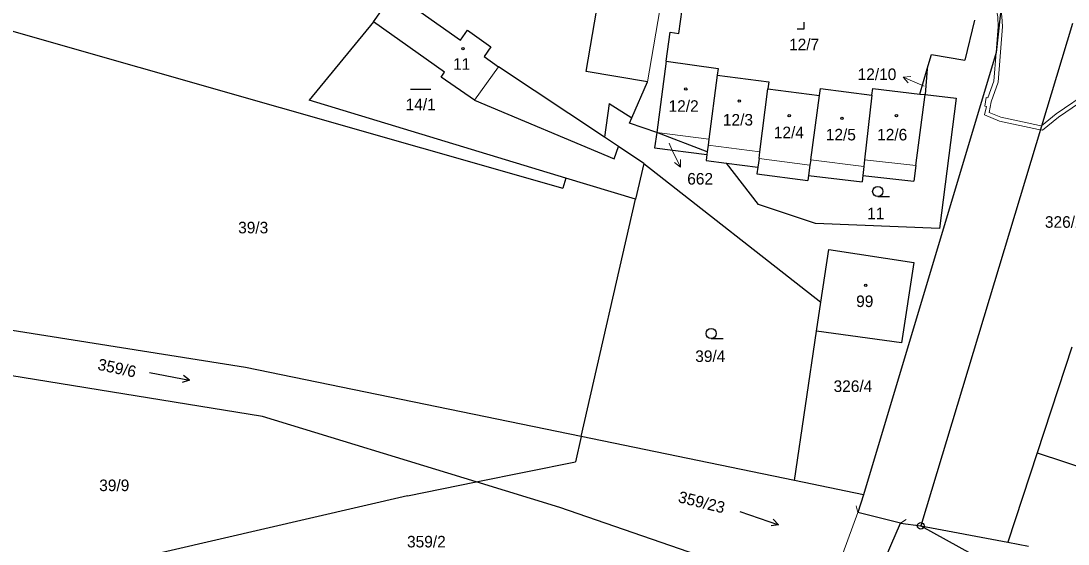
# Model space of a CAD drawing. Extents: x -759947 to -757003, y -1019641 to -1017100.
# Drawn here: x -758095.4 to -757941.4, y -1019052.2 to -1018975.4 of the extents above; entities that cross this region are included whole.
import ezdxf
from ezdxf.enums import TextEntityAlignment as Align

# ---------------------------------------------------------------- set-up
doc = ezdxf.new("R2010")
doc.units = 0
doc.header["$LTSCALE"] = 0.68
for name, color, linetype, lineweight in [('1', 7, 'Continuous', 25), ('13', 7, 'Continuous', 13), ('3', 7, 'Continuous', 25), ('4', 7, 'Continuous', 13), ('5', 7, 'Continuous', 25), ('7', 7, 'Continuous', 13), ('8', 7, 'Continuous', 25)]:
    doc.layers.add(name, color=color, linetype=linetype, lineweight=lineweight)
doc.layers.add('2', color=7, linetype='Continuous')

msp = doc.modelspace()

# ---------------------------------------------------------------- linework, layer by layer
at = {"layer": '1'}
for p, q in [((-757949.4, -1018956.77), (-757951.94, -1018980.02)), ((-758012.27, -1018982.78), (-758008.32, -1018959.61)), ((-757998.62, -1018977.2), (-757997.84, -1018971.35)), ((-758106.97, -1018973.92), (-758015.69, -1018999.93)), ((-758043.52, -1018975.49), (-758052.98, -1018986.98)), ((-758033.09, -1018982.87), (-758043.52, -1018975.49)), ((-757940.73, -1018975.74), (-757963.05, -1019049.56)), ((-757955.12, -1018975.23), (-757956.58, -1018981.14)), ((-758030.72, -1018978.17), (-758029.69, -1018976.72)), ((-758029.69, -1018976.72), (-758026.25, -1018979.16)), ((-758026.25, -1018979.16), (-758027.27, -1018980.6)), ((-758027.27, -1018980.6), (-758025.13, -1018982.11)), ((-757951.94, -1018980.02), (-757971.49, -1019044.98)), ((-757962.12, -1018982.42), (-757961.49, -1018980.28)), ((-757961.49, -1018980.28), (-757956.58, -1018981.14)), ((-758009.57, -1018992.46), (-758025.13, -1018982.11)), ((-758000.48, -1018981.28), (-758001.88, -1018991.74)), ((-758000.48, -1018981.28), (-757992.85, -1018982.36)), ((-757992.85, -1018982.36), (-757992.98, -1018983.35)), ((-757963.2, -1018986.1), (-757962.12, -1018982.42)), ((-757962.12, -1018982.42), (-757962.41, -1018986.19)), ((-758033.6, -1018983.61), (-758033.09, -1018982.87)), ((-758028.67, -1018987.01), (-758033.6, -1018983.61)), ((-758003.24, -1018984.32), (-758012.27, -1018982.78)), ((-757992.98, -1018983.35), (-757994.19, -1018992.73)), ((-757992.98, -1018983.35), (-757985.39, -1018984.33)), ((-758005.54, -1018989.59), (-758003.24, -1018984.32)), ((-757986.7, -1018994.58), (-757985.52, -1018985.32)), ((-757985.39, -1018984.33), (-757985.52, -1018985.32)), ((-757985.52, -1018985.32), (-757977.93, -1018986.3)), ((-757977.93, -1018986.3), (-757977.81, -1018985.3)), ((-757977.81, -1018985.3), (-757970.22, -1018986.28)), ((-757970.22, -1018986.28), (-757970.09, -1018985.29)), ((-757970.09, -1018985.29), (-757963.2, -1018986.1)), ((-758015.22, -1018998.44), (-758052.98, -1018986.98)), ((-758028.67, -1018987.01), (-758008.12, -1018995.64)), ((-757979.23, -1018995.77), (-757977.93, -1018986.3)), ((-757970.22, -1018986.28), (-757971.3, -1018995.77)), ((-757963.76, -1018996.62), (-757962.41, -1018986.19)), ((-757963.2, -1018986.1), (-757962.41, -1018986.19)), ((-757962.41, -1018986.19), (-757957.84, -1018986.73)), ((-758008.85, -1018987.51), (-758009.57, -1018992.46)), ((-758008.85, -1018987.51), (-758005.54, -1018989.59)), ((-758005.89, -1018990.39), (-758005.54, -1018989.59)), ((-758001.88, -1018991.74), (-758005.89, -1018990.39)), ((-758001.88, -1018991.74), (-758002.19, -1018994.02)), ((-757994.44, -1018994.61), (-758001.88, -1018991.74)), ((-758007.5, -1018993.83), (-758009.57, -1018992.46)), ((-757994.19, -1018992.73), (-757994.31, -1018993.59)), ((-758008.12, -1018995.64), (-758007.5, -1018993.83)), ((-758003.78, -1018996.31), (-758007.5, -1018993.83)), ((-758002.19, -1018994.02), (-757994.49, -1018995.01)), ((-757994.44, -1018994.61), (-757994.49, -1018995.01)), ((-757994.31, -1018993.59), (-757994.44, -1018994.61)), ((-757986.83, -1018995.56), (-757986.7, -1018994.58)), ((-758003.78, -1018996.31), (-758004.98, -1019001.55)), ((-758003.78, -1018996.31), (-757977.73, -1019016.71)), ((-757994.49, -1018995.01), (-757994.6, -1018995.87)), ((-757994.6, -1018995.87), (-757991.63, -1018996.26)), ((-757991.63, -1018996.26), (-757987, -1018996.86)), ((-757986.91, -1019002.32), (-757991.63, -1018996.26)), ((-757986.83, -1018995.56), (-757987, -1018996.86)), ((-757979.23, -1018995.77), (-757979.34, -1018996.53)), ((-757971.3, -1018995.77), (-757971.41, -1018996.73)), ((-757987, -1018996.86), (-757987.13, -1018997.84)), ((-757987.13, -1018997.84), (-757979.64, -1018998.81)), ((-757979.34, -1018996.53), (-757979.54, -1018998.05)), ((-757971.41, -1018996.73), (-757971.56, -1018998.06)), ((-757963.76, -1018996.62), (-757964.06, -1018998.9)), ((-758015.22, -1018998.44), (-758015.69, -1018999.93)), ((-758004.98, -1019001.55), (-758015.22, -1018998.44)), ((-757979.54, -1018998.05), (-757979.64, -1018998.81)), ((-757979.54, -1018998.05), (-757971.67, -1018999.02)), ((-757971.56, -1018998.06), (-757971.67, -1018999.02)), ((-757971.56, -1018998.06), (-757964.06, -1018998.9)), ((-758012.99, -1019036.45), (-758004.98, -1019001.55)), ((-757978.53, -1019005.15), (-757986.91, -1019002.32)), ((-757977.73, -1019016.71), (-757976.58, -1019008.96)), ((-757976.58, -1019008.96), (-757964.07, -1019010.84)), ((-757964.07, -1019010.84), (-757965.88, -1019022.65)), ((-758062.35, -1019026.31), (-758120.22, -1019017.1)), ((-757978.36, -1019020.93), (-757977.73, -1019016.71)), ((-757981.62, -1019042.9), (-757978.36, -1019020.93)), ((-757965.88, -1019022.65), (-757978.36, -1019020.93)), ((-757940.84, -1019023.32), (-757945.93, -1019038.84)), ((-758059.87, -1019033.48), (-758107.42, -1019025.81)), ((-758012.99, -1019036.45), (-758062.35, -1019026.31)), ((-758028.41, -1019043.1), (-758059.87, -1019033.48)), ((-758012.99, -1019036.45), (-758013.84, -1019040.15)), ((-757981.62, -1019042.9), (-758012.99, -1019036.45)), ((-757945.93, -1019038.84), (-757950.23, -1019051.96)), ((-757945.93, -1019038.84), (-757935.66, -1019042.2)), ((-758028.41, -1019043.1), (-758013.84, -1019040.15)), ((-758038.51, -1019045.14), (-758028.41, -1019043.1)), ((-758016.14, -1019046.85), (-758028.41, -1019043.1)), ((-757971.49, -1019044.98), (-757981.62, -1019042.9)), ((-758038.51, -1019045.14), (-758080.47, -1019054.84)), ((-757971.49, -1019044.98), (-757972.28, -1019047.6)), ((-757976.98, -1019060.34), (-758016.14, -1019046.85)), ((-757966.03, -1019049.17), (-757972.28, -1019047.6)), ((-757971.99, -1019062.81), (-757966.03, -1019049.17)), ((-757966.03, -1019049.17), (-757963.05, -1019049.56)), ((-757963.05, -1019049.56), (-757950.23, -1019051.96)), ((-757963.05, -1019049.56), (-757891.09, -1019089.05)), ((-757950.23, -1019051.96), (-757947.21, -1019052.53))]:
    msp.add_line(p, q, dxfattribs=at)
for points in [[(-758043.52, -1018975.49), (-758040.52, -1018971.25), (-758030.72, -1018978.17)], [(-758000.48, -1018981.28), (-757999.91, -1018977.03), (-757998.62, -1018977.2)], [(-757957.84, -1018986.73), (-757960.29, -1019005.87), (-757978.53, -1019005.15)]]:
    msp.add_lwpolyline(points, dxfattribs=at)
at = {"layer": '13'}
for points in [[(-757949.75, -1018951.37), (-757949.89, -1018951.35), (-757949.9, -1018951.2), (-757950.15, -1018951.21), (-757950.1, -1018952.08), (-757949.85, -1018952.07), (-757949.86, -1018951.96), (-757949.76, -1018951.97), (-757949.97, -1018955.93), (-757950.52, -1018963.51), (-757951.84, -1018974.04), (-757951.73, -1018974.77), (-757951.64, -1018976.16), (-757951.94, -1018980.02), (-757949.4, -1018956.77), (-757949.71, -1018945.51)], [(-757949.92, -1018963.57), (-757949.4, -1018956.77), (-757951.94, -1018980.02), (-757952.28, -1018984.22), (-757953.17, -1018986.65), (-757953.42, -1018986.61), (-757953.62, -1018987.89), (-757953.38, -1018987.93), (-757953.69, -1018989.17), (-757951.47, -1018990.08), (-757945.75, -1018991.29), (-757945.45, -1018991.35), (-757945.27, -1018990.76), (-757945.3, -1018990.78), (-757945.59, -1018990.71), (-757951.29, -1018989.5), (-757953.01, -1018988.81), (-757952.7, -1018987.26), (-757951.68, -1018984.34), (-757951.04, -1018976.16), (-757951.13, -1018974.71), (-757951.24, -1018974.04)], [(-757930.45, -1018979.41), (-757934.39, -1018982.12), (-757938.07, -1018985.58), (-757943.15, -1018989.03), (-757945.27, -1018990.76), (-757945.45, -1018991.35), (-757945.14, -1018991.42), (-757942.79, -1018989.51), (-757937.69, -1018986.04), (-757934.01, -1018982.58), (-757930.29, -1018980.03), (-757928.65, -1018980.19), (-757928.46, -1018979.61)]]:
    msp.add_lwpolyline(points, close=True, dxfattribs=at)
at = {"layer": '3'}
for p, q in [((-758038.088, -1018985.36), (-758035.088, -1018985.36)), ((-757969.373, -1019001.18), (-757967.623, -1019001.18)), ((-757993.863, -1019022.04), (-757992.113, -1019022.04)), ((-758070.6, -1019028.164), (-758071.655, -1019028.47)), ((-757983.97, -1019049.39), (-757985.057, -1019049.546))]:
    msp.add_line(p, q, dxfattribs=at)
for points in [[(-757981.201, -1018976.54), (-757980.2, -1018976.54), (-757980.2, -1018975.54)], [(-758076.49, -1019027.019), (-758070.6, -1019028.164), (-758071.463, -1019027.485)], [(-757989.643, -1019047.437), (-757983.97, -1019049.39), (-757984.731, -1019048.598)]]:
    msp.add_lwpolyline(points, dxfattribs=at)
for centre in [(-757969.3729, -1019000.4298), (-757993.8629, -1019021.2898)]:
    msp.add_circle(centre, 0.75, dxfattribs=at)
at = {"layer": '4'}
for p, q in [((-757998.8, -1018958.51), (-758003.24, -1018984.32)), ((-758028.67, -1018987.01), (-758025.13, -1018982.11)), ((-757994.19, -1018992.73), (-758001.88, -1018991.74)), ((-757994.31, -1018993.59), (-757986.7, -1018994.58)), ((-757986.83, -1018995.56), (-757979.34, -1018996.53)), ((-757971.41, -1018996.73), (-757979.23, -1018995.77)), ((-757963.76, -1018996.62), (-757971.3, -1018995.77)), ((-757972.538, -1019046.634), (-757972.28, -1019047.599)), ((-757976.98, -1019060.34), (-757972.28, -1019047.6)), ((-757965.191, -1019048.626), (-757966.029, -1019049.17))]:
    msp.add_line(p, q, dxfattribs=at)
at = {"layer": '5'}
for centre in [(-758030.3768, -1018979.4492), (-757997.5968, -1018985.3492), (-757989.7368, -1018987.1392), (-757982.3968, -1018989.2592), (-757974.6368, -1018989.6892), (-757966.6168, -1018989.2992), (-757971.1368, -1019014.2092)]:
    msp.add_circle(centre, 0.175, dxfattribs=at)
at = {"layer": '7'}
for p, q in [((-757965.632, -1018983.607), (-757964.906, -1018984.46)), ((-757998.374, -1018996.837), (-757998.363, -1018995.718))]:
    msp.add_line(p, q, dxfattribs=at)
for points in [[(-757962.53, -1018984.92), (-757962.87, -1018984.78), (-757965.632, -1018983.607), (-757964.515, -1018983.538)], [(-758000.07, -1018993.34), (-757999.69, -1018994.14), (-757998.374, -1018996.837), (-757999.264, -1018996.157)]]:
    msp.add_lwpolyline(points, dxfattribs=at)
at = {"layer": '8'}
for radius in [0.5, 0.0303]:
    msp.add_circle((-757963.05, -1019049.5599), radius, dxfattribs=at)

# ---------------------------------------------------------------- texts
at = {"layer": '2'}
for s, p in [('12/7', (-757980.199, -1018979.665)), ('11', (-758030.569, -1018982.535)), ('14/1', (-758036.589, -1018988.485)), ('12/2', (-757997.919, -1018988.715)), ('12/3', (-757989.929, -1018990.735)), ('12/4', (-757982.439, -1018992.595)), ('12/5', (-757974.799, -1018992.915)), ('12/6', (-757967.249, -1018992.915)), ('11', (-757969.669, -1019004.495)), ('326/21', (-757941.31, -1019005.755)), ('39/3', (-758061.219, -1019006.575)), ('99', (-757971.279, -1019017.405)), ('39/4', (-757993.999, -1019025.475)), ('326/4', (-757973.02, -1019029.885)), ('39/9', (-758081.649, -1019044.455)), ('359/2', (-758035.75, -1019052.735))]:
    msp.add_text(s, height=1.7, dxfattribs=at).set_placement(p, align=Align.CENTER)
msp.add_text('12/10', height=1.7, dxfattribs=at).set_placement((-757966.64, -1018984.045), align=Align.RIGHT)
msp.add_text('662', height=1.7, dxfattribs=at).set_placement((-757997.39, -1018999.405))
for s, rotation, p in [('359/6', 348, (-758081.4182, -1019027.1947)), ('359/23', 346, (-757995.4681, -1019046.9076))]:
    msp.add_text(s, height=1.7, rotation=rotation, dxfattribs=at).set_placement(p, align=Align.CENTER)

doc.saveas('drawing.dxf')
